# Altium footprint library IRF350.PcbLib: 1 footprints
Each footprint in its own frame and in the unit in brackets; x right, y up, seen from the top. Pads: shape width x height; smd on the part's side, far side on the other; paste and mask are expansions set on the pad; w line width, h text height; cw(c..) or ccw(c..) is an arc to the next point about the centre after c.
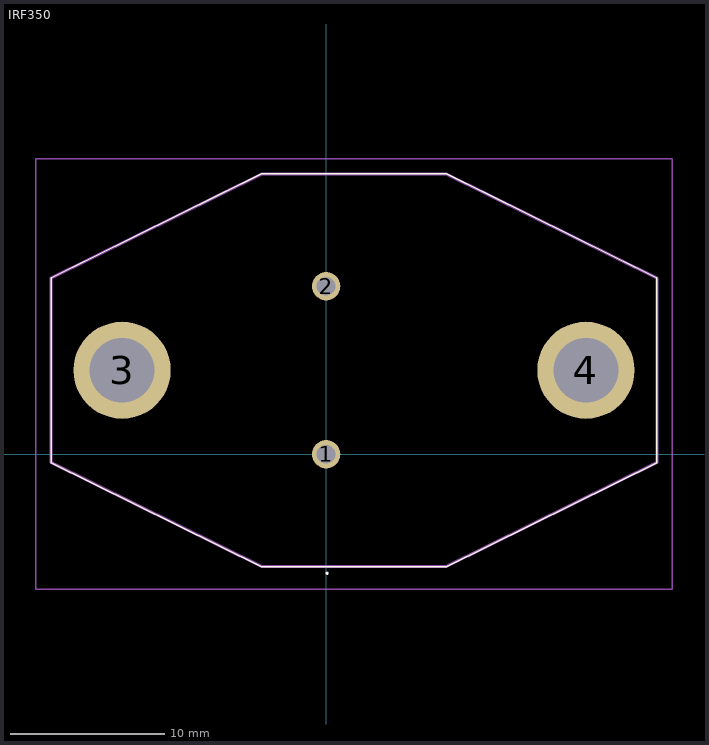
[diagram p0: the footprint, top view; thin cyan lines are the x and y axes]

## IRF350 [mm]
pads (4):
  round 1.845 hole 1.23: 1(0,0) 2(0,10.92)
  round 6.322 hole 4.215: 3(-13.26,5.46) 4(16.89,5.46)
Top Overlay:
  lines w0.1: -0.001,-7.741 cw(c0.058,-7.741) 0.116,-7.741 ; 0.015,-7.74 0.015,-7.74 ; 0.015,-7.74 ccw(c0.065,-7.74) 0.115,-7.74 ; 0.115,-7.74 0.115,-7.74 ; -17.87,-0.54 -4.185,-7.305 7.815,-7.305 21.5,-0.54 21.5,11.46 7.815,18.225 -4.185,18.225 -17.87,11.46 -17.87,-0.54
Mechanical 15:
  lines w0.2: -17.87,-0.54 -17.87,11.46 -4.185,18.225 7.815,18.225 21.5,11.46 21.5,-0.54 7.815,-7.305 -4.185,-7.305 -17.87,-0.54
Mechanical 20:
  lines w0.1: -18.87,-8.79 22.5,-8.79 22.5,19.225 -18.87,19.225 -18.87,-8.79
